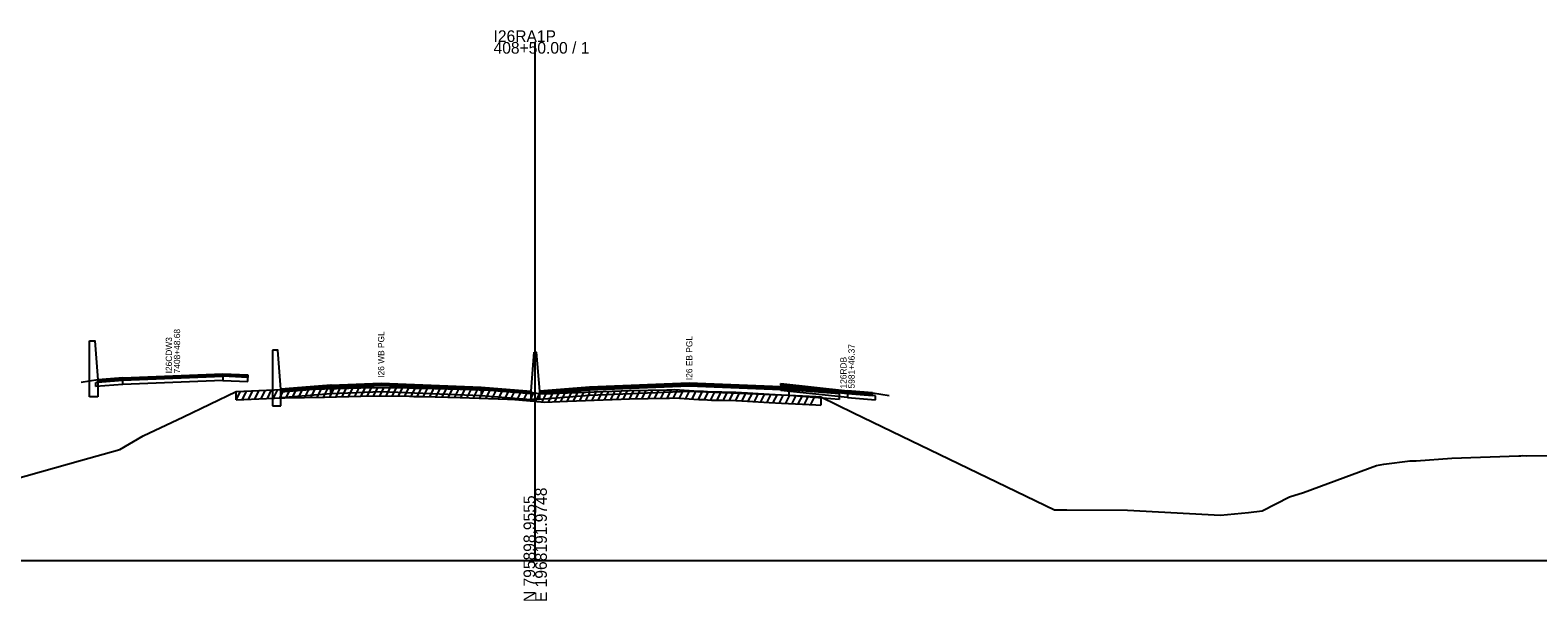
# Model space of a CAD drawing. Extents: x 1017 to 19997, y -1947 to 50737.
# Drawn here: x 16478.7 to 16840.8, y 8490.3 to 8627.3 of the extents above; entities that cross this region are included whole.
import ezdxf

# ---------------------------------------------------------------- set-up
doc = ezdxf.new("R2010")
doc.units = 0
for name, color, linetype in [('RD_GPK_XS_Cell', 7, 'Continuous'), ('RD_XS_Base', 7, 'Continuous'), ('RD_XS_ExGround', 7, 'Continuous'), ('RD_XS_ExPaveRet', 7, 'Continuous'), ('RD_XS_Greenside', 7, 'Continuous'), ('RD_XS_MedBWall', 7, 'Continuous'), ('RD_XS_Pave', 7, 'Continuous'), ('RD_XS_PaveOvlay', 7, 'Continuous'), ('RD_XS_TX_Notes', 7, 'Continuous')]:
    doc.layers.add(name, color=color, linetype=linetype)

msp = doc.modelspace()

# ---------------------------------------------------------------- linework, layer by layer
at = {"layer": 'RD_GPK_XS_Cell'}
for p, q in [((16600, 8500), (16600, 8624.42)), ((16000, 8500), (16600, 8500)), ((16600, 8500), (17200, 8500))]:
    msp.add_line(p, q, dxfattribs=at)
at = {"layer": 'RD_XS_Base'}
for points in [[(16494.5, 8542.71), (16495, 8542.75), (16501, 8543.23)], [(16494.5, 8541.71), (16494.5, 8542.71)], [(16501, 8542.23), (16494.5, 8541.71)], [(16501, 8542.23), (16501, 8543.23)], [(16525, 8543.19), (16513, 8542.71), (16501, 8542.23)], [(16525, 8544.19), (16525, 8543.19)], [(16525, 8543.19), (16531, 8542.93)], [(16531, 8542.93), (16531, 8543.93)], [(16550.95, 8541.38), (16538.95, 8540.42)], [(16550.95, 8540.04), (16550.95, 8541.38)], [(16551, 8541.38), (16551, 8540.04)], [(16659, 8540.79), (16659, 8541.79)], [(16538.95, 8540.42), (16538.95, 8539.08)], [(16538.95, 8539.08), (16550.95, 8540.04)], [(16551, 8540.04), (16550.95, 8540.04)], [(16551, 8540.04), (16563, 8540.54), (16587, 8539.57)], [(16599, 8539.97), (16587, 8540.91)], [(16587, 8540.91), (16587, 8539.57)], [(16587, 8539.57), (16599, 8538.63)], [(16599, 8538.63), (16599, 8539.97)], [(16601, 8538.63), (16601, 8539.97)], [(16613, 8539.57), (16601, 8538.63)], [(16613, 8539.57), (16613, 8540.91)], [(16660.95, 8539.57), (16637, 8540.54), (16613, 8539.57)], [(16675.01, 8539.07), (16659, 8540.79)], [(16660.95, 8539.57), (16660.95, 8540.91)], [(16661, 8539.57), (16660.95, 8539.57)], [(16661, 8539.57), (16661, 8540.91)], [(16673, 8538.61), (16661, 8539.57)], [(16673, 8539.95), (16673, 8538.61)], [(16675.01, 8540.07), (16675.01, 8539.07)], [(16681.72, 8539.52), (16681.02, 8539.58), (16675.01, 8540.07)], [(16675.01, 8539.07), (16681.72, 8538.52)], [(16681.72, 8538.52), (16681.72, 8539.52)]]:
    msp.add_lwpolyline(points, dxfattribs=at)
at = {"layer": 'RD_XS_ExGround'}
msp.add_lwpolyline([(16468.32, 8517.7), (16490.82, 8523.98), (16500.27, 8526.62), (16505.88, 8529.93), (16515.54, 8534.5), (16528.18, 8540.53), (16535.44, 8540.89), (16537.39, 8540.98), (16539.91, 8541.04), (16549.41, 8541.22), (16558.09, 8541.41), (16561.16, 8541.47), (16569.8, 8541.39), (16570.89, 8541.37), (16573.02, 8541.33), (16581.95, 8541.13), (16593.38, 8540.71), (16594.08, 8540.68), (16595.11, 8540.6), (16599.73, 8540.22), (16600.43, 8540.18), (16602.35, 8540.01), (16605.89, 8540.15), (16607.76, 8540.23), (16618.52, 8540.66), (16620.66, 8540.74), (16622.68, 8540.78), (16631.65, 8540.92), (16632.24, 8540.96), (16633.42, 8541), (16639.29, 8540.63), (16640.4, 8540.59), (16642.37, 8540.5), (16642.78, 8540.49), (16643.09, 8540.48), (16643.77, 8540.46), (16644.13, 8540.46), (16644.52, 8540.48), (16644.85, 8540.48), (16648.19, 8540.42), (16650.99, 8540.25), (16656.15, 8539.94), (16659.14, 8539.78), (16664.19, 8539.49), (16667.4, 8539.35), (16668.59, 8539.3), (16676.46, 8535.44), (16724.7, 8512.17), (16727.69, 8512.15), (16742.22, 8512.03), (16764.53, 8510.87), (16764.56, 8510.88), (16771.26, 8511.54), (16774.55, 8511.91), (16781.17, 8515.25), (16784.47, 8516.31), (16802.05, 8522.82), (16803.77, 8523.11), (16810.13, 8523.92), (16811.52, 8523.94), (16820.15, 8524.58), (16836.22, 8525.12), (16836.7, 8525.14), (16837.16, 8525.16), (16838.1, 8525.14), (16851.73, 8525.26)], dxfattribs=at)
at = {"layer": 'RD_XS_ExPaveRet'}
for p, q in [((16540.18, 8539.04), (16541.19, 8541.06)), ((16541.68, 8539.07), (16542.69, 8541.09)), ((16543.18, 8539.1), (16544.19, 8541.12)), ((16544.68, 8539.13), (16545.69, 8541.15)), ((16546.18, 8539.16), (16547.19, 8541.18)), ((16547.68, 8539.19), (16548.69, 8541.21)), ((16549.18, 8539.22), (16550.19, 8541.24)), ((16550.68, 8539.25), (16551.69, 8541.27)), ((16552.18, 8539.28), (16553.19, 8541.31)), ((16553.68, 8539.32), (16554.69, 8541.34)), ((16555.18, 8539.35), (16556.19, 8541.37)), ((16556.68, 8539.38), (16557.69, 8541.4)), ((16558.18, 8539.41), (16559.19, 8541.43)), ((16559.68, 8539.44), (16560.69, 8541.46)), ((16561.18, 8539.47), (16562.17, 8541.46)), ((16562.68, 8539.46), (16563.67, 8541.45)), ((16564.18, 8539.44), (16565.17, 8541.43)), ((16565.68, 8539.43), (16566.67, 8541.42)), ((16567.18, 8539.41), (16568.17, 8541.4)), ((16568.68, 8539.4), (16569.67, 8541.39)), ((16570.18, 8539.38), (16571.17, 8541.37)), ((16571.68, 8539.36), (16572.67, 8541.34)), ((16573.18, 8539.33), (16574.17, 8541.3)), ((16574.68, 8539.29), (16575.67, 8541.27)), ((16576.18, 8539.26), (16577.17, 8541.24)), ((16577.68, 8539.23), (16578.67, 8541.2)), ((16579.18, 8539.19), (16580.17, 8541.17)), ((16580.68, 8539.16), (16581.67, 8541.14)), ((16582.18, 8539.12), (16583.16, 8541.09)), ((16528.18, 8538.53), (16529.2, 8540.58)), ((16528.18, 8538.53), (16528.18, 8540.53)), ((16528.18, 8538.53), (16535.44, 8538.89)), ((16529.68, 8538.6), (16530.7, 8540.65)), ((16531.18, 8538.68), (16532.2, 8540.73)), ((16532.68, 8538.75), (16533.7, 8540.8)), ((16534.18, 8538.83), (16535.2, 8540.88)), ((16535.44, 8538.89), (16537.39, 8538.98)), ((16535.68, 8538.9), (16536.7, 8540.95)), ((16537.18, 8538.97), (16538.19, 8541)), ((16537.39, 8538.98), (16539.91, 8539.04)), ((16538.68, 8539.01), (16539.69, 8541.03)), ((16539.91, 8539.04), (16549.41, 8539.22)), ((16549.41, 8539.22), (16558.09, 8539.41)), ((16558.09, 8539.41), (16561.16, 8539.47)), ((16561.16, 8539.47), (16569.8, 8539.39)), ((16569.8, 8539.39), (16570.89, 8539.37)), ((16570.89, 8539.37), (16573.02, 8539.33)), ((16573.02, 8539.33), (16581.95, 8539.13)), ((16581.95, 8539.13), (16593.38, 8538.71)), ((16583.68, 8539.07), (16584.66, 8541.03)), ((16585.18, 8539.01), (16586.16, 8540.97)), ((16586.68, 8538.95), (16587.66, 8540.92)), ((16588.18, 8538.9), (16589.16, 8540.86)), ((16589.68, 8538.84), (16590.66, 8540.81)), ((16591.18, 8538.79), (16592.16, 8540.75)), ((16592.68, 8538.73), (16593.66, 8540.7)), ((16593.38, 8538.71), (16594.08, 8538.68)), ((16594.08, 8538.68), (16595.11, 8538.6)), ((16594.18, 8538.67), (16595.14, 8540.6)), ((16595.11, 8538.6), (16599.73, 8538.22)), ((16595.68, 8538.55), (16596.64, 8540.47)), ((16597.18, 8538.43), (16598.14, 8540.35)), ((16598.68, 8538.31), (16599.64, 8540.23)), ((16599.73, 8538.22), (16600.43, 8538.18)), ((16600.18, 8538.2), (16601.14, 8540.12)), ((16600.43, 8538.18), (16602.35, 8538.01)), ((16601.68, 8538.07), (16602.65, 8540.02)), ((16602.35, 8538.01), (16605.89, 8538.15)), ((16603.18, 8538.04), (16604.2, 8540.08)), ((16604.68, 8538.1), (16605.7, 8540.14)), ((16605.89, 8538.15), (16607.76, 8538.23)), ((16606.18, 8538.16), (16607.2, 8540.2)), ((16607.68, 8538.22), (16608.7, 8540.26)), ((16607.76, 8538.23), (16618.52, 8538.66)), ((16609.18, 8538.28), (16610.2, 8540.32)), ((16610.68, 8538.34), (16611.7, 8540.38)), ((16612.18, 8538.4), (16613.2, 8540.44)), ((16613.68, 8538.46), (16614.7, 8540.51)), ((16615.18, 8538.52), (16616.2, 8540.57)), ((16616.68, 8538.58), (16617.7, 8540.63)), ((16618.18, 8538.64), (16619.2, 8540.68)), ((16618.52, 8538.66), (16620.66, 8538.74)), ((16619.68, 8538.7), (16620.7, 8540.74)), ((16620.66, 8538.74), (16622.68, 8538.78)), ((16621.18, 8538.75), (16622.19, 8540.77)), ((16622.68, 8538.78), (16623.68, 8540.8)), ((16622.68, 8538.78), (16631.65, 8538.92)), ((16624.18, 8538.8), (16625.18, 8540.82)), ((16625.68, 8538.83), (16626.68, 8540.84)), ((16627.18, 8538.85), (16628.18, 8540.87)), ((16628.68, 8538.88), (16629.68, 8540.89)), ((16630.18, 8538.9), (16631.18, 8540.92)), ((16631.65, 8538.92), (16632.24, 8538.96)), ((16631.68, 8538.93), (16632.7, 8540.97)), ((16632.24, 8538.96), (16633.42, 8539)), ((16633.18, 8538.99), (16634.16, 8540.95)), ((16633.42, 8539), (16639.29, 8538.63)), ((16634.68, 8538.92), (16635.65, 8540.86)), ((16636.18, 8538.83), (16637.15, 8540.77)), ((16637.68, 8538.73), (16638.65, 8540.67)), ((16639.18, 8538.64), (16640.16, 8540.6)), ((16639.29, 8538.63), (16640.4, 8538.59)), ((16640.4, 8538.59), (16642.37, 8538.5)), ((16640.68, 8538.58), (16641.65, 8540.53)), ((16642.18, 8538.51), (16643.16, 8540.48)), ((16642.37, 8538.5), (16642.78, 8538.49)), ((16642.78, 8538.49), (16643.09, 8538.48)), ((16643.09, 8538.48), (16643.77, 8538.46)), ((16643.68, 8538.46), (16644.69, 8540.48)), ((16643.77, 8538.46), (16644.13, 8538.46)), ((16644.13, 8538.46), (16644.52, 8538.48)), ((16644.52, 8538.48), (16644.85, 8538.48)), ((16644.85, 8538.48), (16648.19, 8538.42)), ((16645.18, 8538.48), (16646.17, 8540.46)), ((16646.68, 8538.45), (16647.67, 8540.43)), ((16648.18, 8538.42), (16649.15, 8540.36)), ((16648.19, 8538.42), (16650.99, 8538.25)), ((16649.68, 8538.33), (16650.65, 8540.27)), ((16650.99, 8538.25), (16656.15, 8537.94)), ((16651.18, 8538.24), (16652.15, 8540.18)), ((16652.68, 8538.15), (16653.65, 8540.09)), ((16654.18, 8538.06), (16655.15, 8540)), ((16655.68, 8537.97), (16656.65, 8539.91)), ((16656.15, 8537.94), (16659.14, 8537.78)), ((16657.18, 8537.89), (16658.15, 8539.83)), ((16658.68, 8537.8), (16659.65, 8539.75)), ((16659.14, 8537.78), (16664.19, 8537.49)), ((16660.18, 8537.72), (16661.15, 8539.66)), ((16661.68, 8537.63), (16662.65, 8539.58)), ((16663.18, 8537.55), (16664.15, 8539.49)), ((16664.19, 8537.49), (16667.4, 8537.35)), ((16664.68, 8537.47), (16665.66, 8539.43)), ((16666.18, 8537.4), (16667.16, 8539.36)), ((16668.59, 8539.3), (16668.59, 8537.3)), ((16667.4, 8537.35), (16668.59, 8537.3))]:
    msp.add_line(p, q, dxfattribs=at)
at = {"layer": 'RD_XS_Greenside'}
for points in [[(16495, 8543.38), (16491, 8542.74)], [(16681.02, 8540.22), (16685.02, 8539.57)]]:
    msp.add_lwpolyline(points, dxfattribs=at)
at = {"layer": 'RD_XS_MedBWall'}
for points in [[(16493, 8539.24), (16493, 8552.72)], [(16493, 8552.72), (16494.25, 8552.72), (16495, 8543.38)], [(16538.95, 8541.1), (16538.2, 8550.44), (16536.95, 8550.44)], [(16536.95, 8550.44), (16536.95, 8537.1)], [(16599, 8540.62), (16599.75, 8549.96)], [(16599.75, 8549.96), (16600.25, 8549.96), (16601, 8540.62)], [(16495, 8543.38), (16495, 8539.24)], [(16538.95, 8537.1), (16538.95, 8541.1)], [(16495, 8539.24), (16493, 8539.24)], [(16599, 8538.62), (16599, 8539.97), (16599, 8540.62)], [(16601, 8538.62), (16599, 8538.62)], [(16601, 8540.62), (16601, 8539.97), (16601, 8538.62)], [(16536.95, 8537.1), (16538.95, 8537.1)]]:
    msp.add_lwpolyline(points, dxfattribs=at)
at = {"layer": 'RD_XS_Pave'}
for points in [[(16495, 8543.07), (16501, 8543.55)], [(16501, 8543.23), (16495, 8542.75)], [(16495, 8542.75), (16495, 8543.07)], [(16525, 8544.51), (16513, 8544.03), (16501, 8543.55)], [(16501, 8543.23), (16513, 8543.71), (16525, 8544.19)], [(16501, 8543.55), (16501, 8543.23)], [(16525, 8544.19), (16525, 8544.51)], [(16525, 8544.51), (16531, 8544.26)], [(16531, 8543.93), (16525, 8544.19)], [(16531, 8544.26), (16531, 8543.93)], [(16550.95, 8541.72), (16538.95, 8540.76)], [(16550.95, 8541.72), (16551, 8541.72)], [(16550.95, 8541.38), (16550.95, 8541.72)], [(16551, 8541.38), (16550.95, 8541.38)], [(16587, 8540.91), (16563, 8541.88), (16551, 8541.38)], [(16551, 8541.72), (16551, 8541.38)], [(16587, 8541.25), (16587, 8540.91)], [(16587, 8541.25), (16599, 8540.31)], [(16660.95, 8541.25), (16637, 8542.21), (16613, 8541.25)], [(16613, 8540.91), (16637, 8541.88), (16660.95, 8540.91)], [(16613, 8541.25), (16613, 8540.91)], [(16675.01, 8540.39), (16659, 8542.11)], [(16659, 8542.11), (16659, 8541.79)], [(16659, 8541.79), (16675.01, 8540.07)], [(16660.95, 8541.25), (16661, 8541.25)], [(16660.95, 8540.91), (16660.95, 8541.25)], [(16661, 8541.25), (16661, 8540.91)], [(16538.95, 8540.76), (16538.95, 8540.42)], [(16599, 8540.31), (16599, 8539.97)], [(16601, 8539.97), (16613, 8540.91)], [(16601, 8540.31), (16601, 8539.97)], [(16661, 8540.91), (16660.95, 8540.91)], [(16673, 8539.95), (16661, 8540.91)], [(16673, 8540.29), (16673, 8539.95)], [(16675.01, 8540.07), (16675.01, 8540.39)], [(16681.02, 8539.9), (16675.01, 8540.39)], [(16675.01, 8540.07), (16681.02, 8539.58)], [(16681.02, 8539.58), (16681.02, 8539.9)]]:
    msp.add_lwpolyline(points, dxfattribs=at)
at = {"layer": 'RD_XS_PaveOvlay'}
for points in [[(16501, 8543.86), (16513, 8544.34), (16525, 8544.82)], [(16525, 8544.82), (16525, 8544.51)], [(16525, 8544.82), (16531, 8544.58)], [(16501, 8543.86), (16495, 8543.38)], [(16495, 8543.38), (16495, 8543.07)], [(16501, 8543.55), (16501, 8543.86)], [(16531, 8544.58), (16531, 8544.26)], [(16550.95, 8542.06), (16538.95, 8541.1)], [(16538.95, 8541.1), (16538.95, 8540.76)], [(16551, 8542.06), (16550.95, 8542.06)], [(16550.95, 8542.06), (16550.95, 8541.72)], [(16551, 8542.06), (16563, 8542.54), (16587, 8541.58)], [(16587, 8541.25), (16563, 8542.21), (16551, 8541.72)], [(16551, 8541.72), (16551, 8542.06)], [(16587, 8541.58), (16587, 8541.25)], [(16587, 8541.58), (16599, 8540.62)], [(16613, 8541.58), (16601, 8540.62)], [(16601, 8540.31), (16613, 8541.25)], [(16660.95, 8541.59), (16637, 8542.54), (16613, 8541.58)], [(16613, 8541.25), (16613, 8541.58)], [(16659, 8542.43), (16675.01, 8540.71)], [(16659, 8542.11), (16659, 8542.43)], [(16660.95, 8541.59), (16661, 8541.58)], [(16660.95, 8541.25), (16660.95, 8541.59)], [(16661, 8541.58), (16673, 8540.62)], [(16661, 8541.25), (16661, 8541.58)], [(16673, 8540.29), (16661, 8541.25)], [(16599, 8540.62), (16599, 8540.31)], [(16601, 8540.62), (16601, 8540.31)], [(16673, 8540.62), (16673, 8540.29)], [(16675.01, 8540.71), (16675.01, 8540.39)], [(16681.02, 8540.22), (16675.01, 8540.71)], [(16681.02, 8539.9), (16681.02, 8540.22)]]:
    msp.add_lwpolyline(points, dxfattribs=at)

# ---------------------------------------------------------------- texts
at = {"layer": 'RD_GPK_XS_Cell'}
for s, p in [('408+50.00 / 1', (16590, 8621.62)), ('I26RA1P', (16590, 8624.42))]:
    msp.add_text(s, height=2.8, dxfattribs=at).set_placement(p)
for s, p in [('E 1968191.9748', (16602.8, 8490)), ('N 795898.9555', (16600, 8490))]:
    msp.add_text(s, height=2.8, rotation=90, dxfattribs=at).set_placement(p)
at = {"layer": 'RD_XS_TX_Notes'}
for s, p in [(' I26CDW3', (16512.78, 8544.34)), (' 7408+48.68', (16514.73, 8544.34)), ('I26 WB PGL', (16563.75, 8543.85)), ('I26 EB PGL', (16637.75, 8543.28)), (' 126RDB', (16674.76, 8540.71)), (' 5981+46.37', (16676.71, 8540.71))]:
    msp.add_text(s, height=1.5, rotation=90, dxfattribs=at).set_placement(p)

doc.saveas('drawing.dxf')
